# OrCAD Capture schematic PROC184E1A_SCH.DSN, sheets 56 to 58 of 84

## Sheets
56 60. RGMII1: size C; title: RGMII1; note: PROC184_SCH
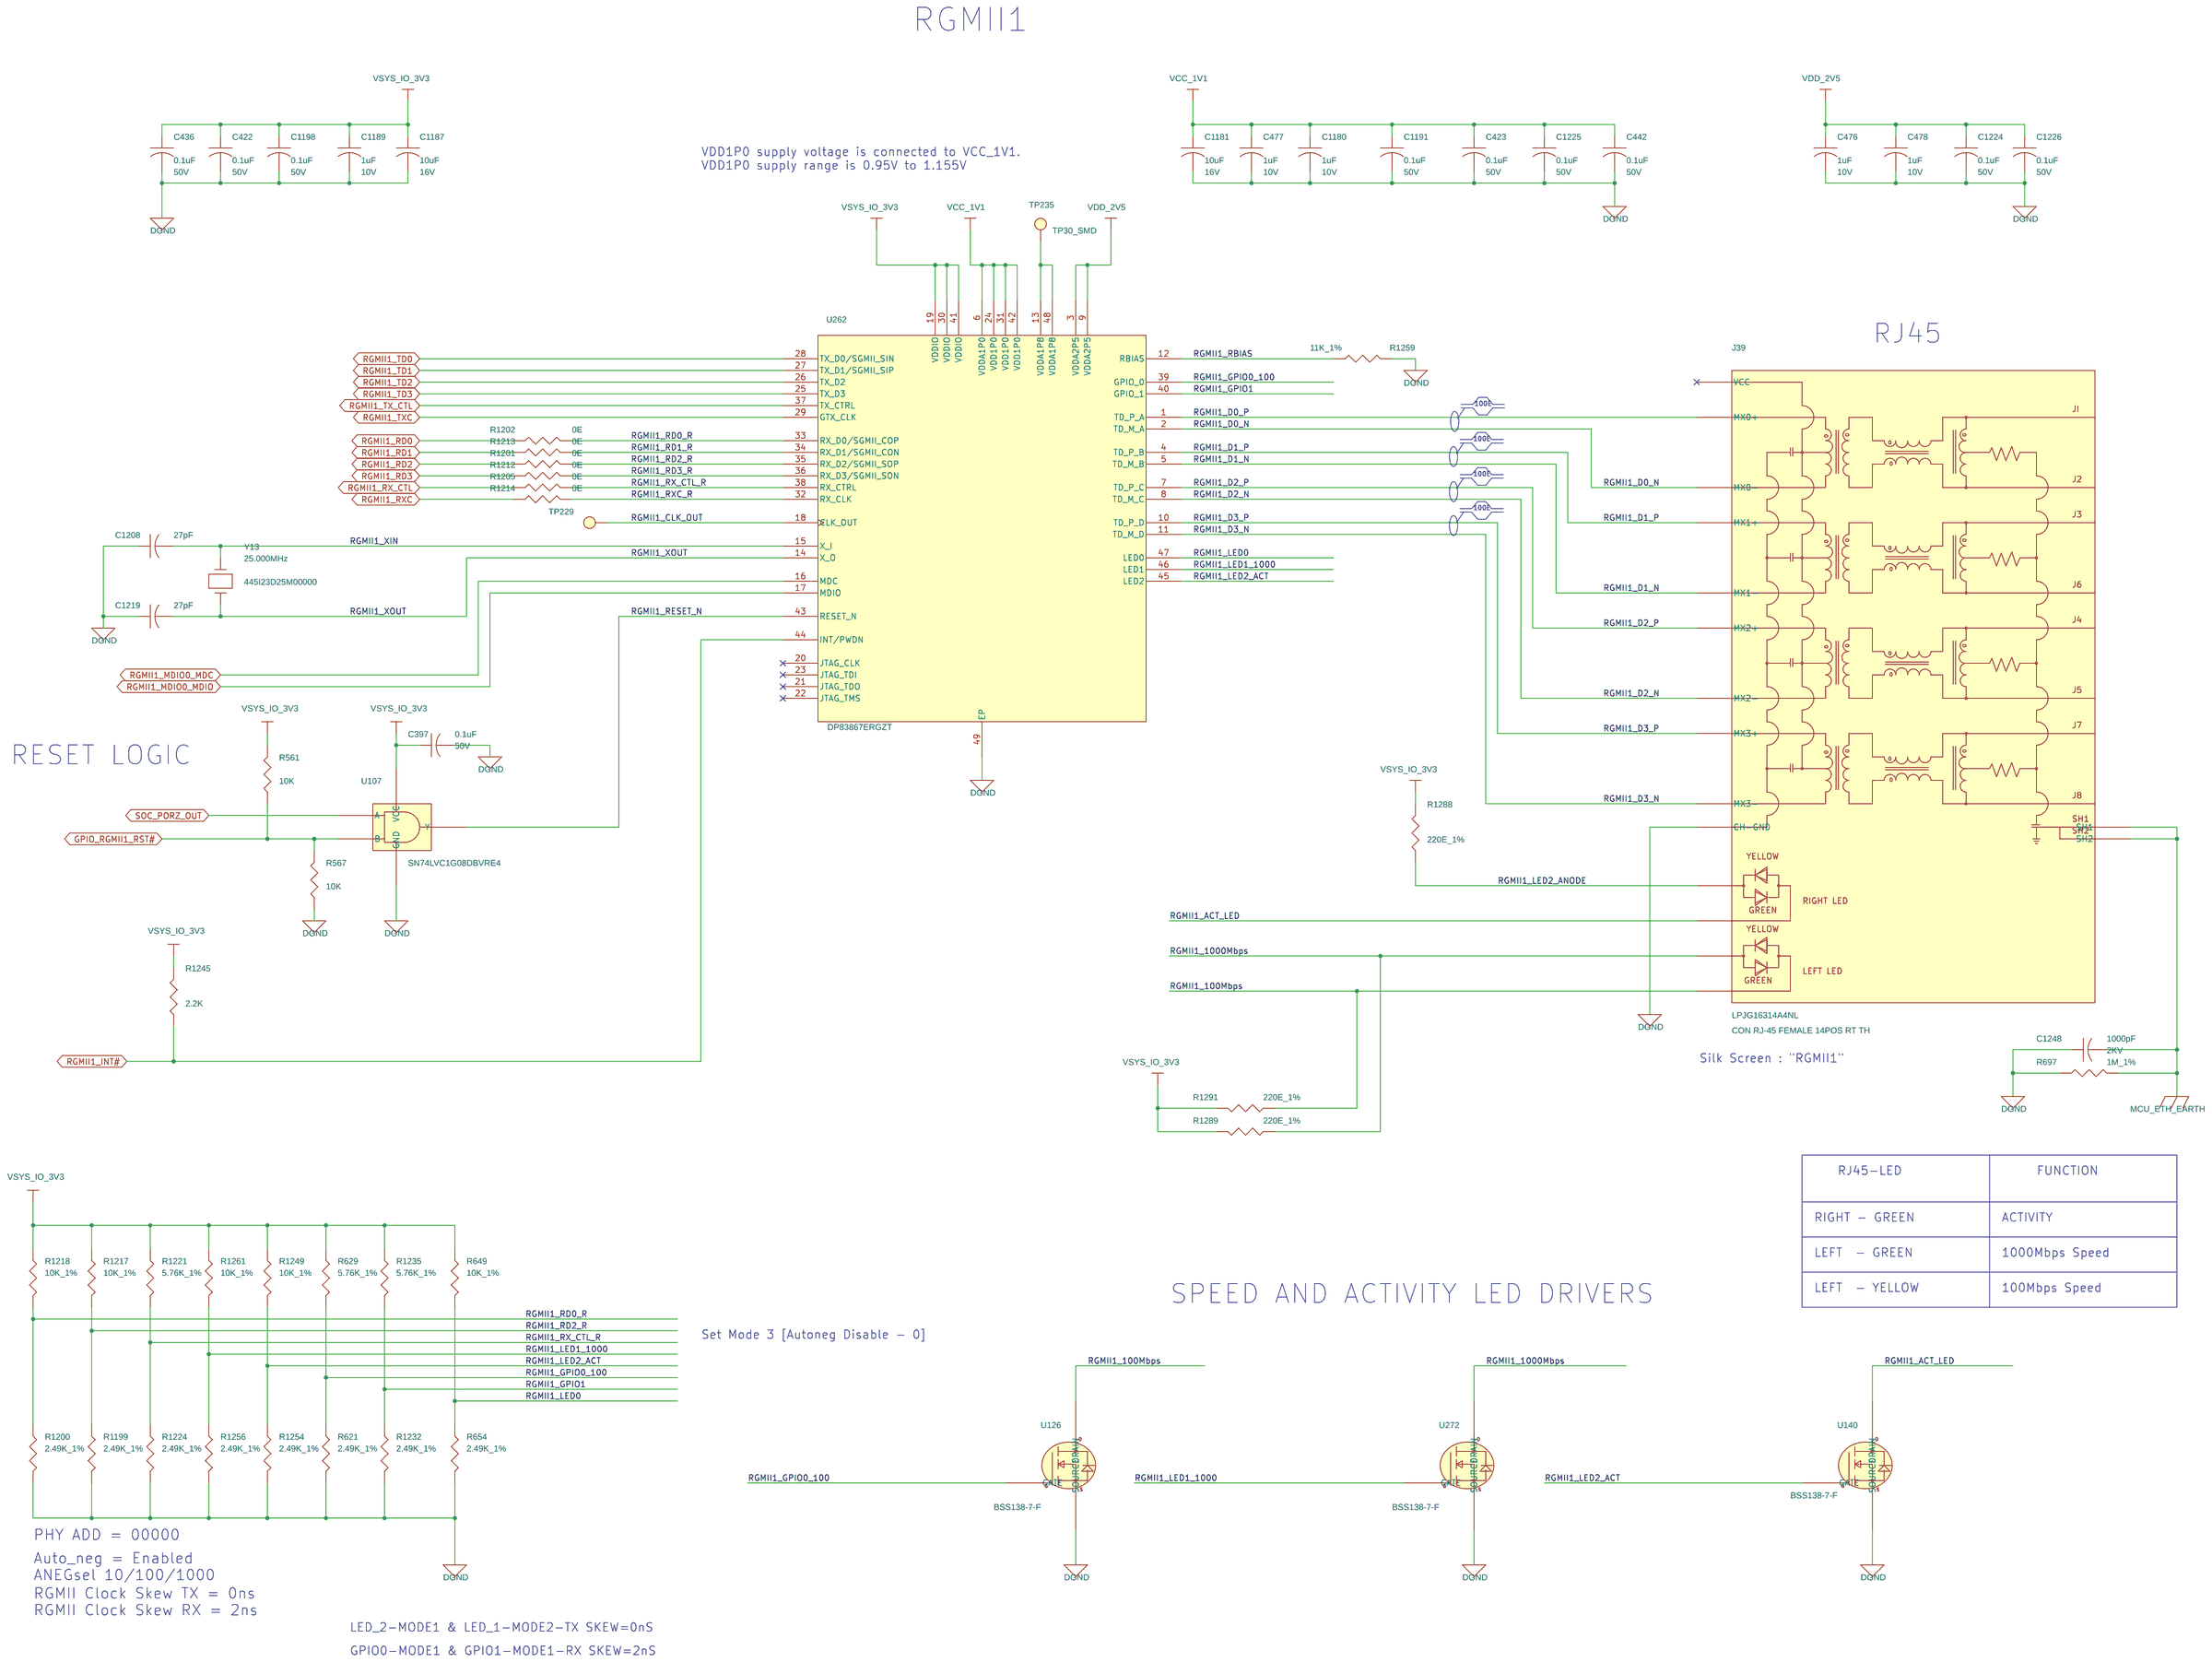
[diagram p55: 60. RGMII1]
57 65. DISPLAY PORT INTERFACE: size C; title: DISPLAY PORT INTERFACE; note: PROC184_SCH
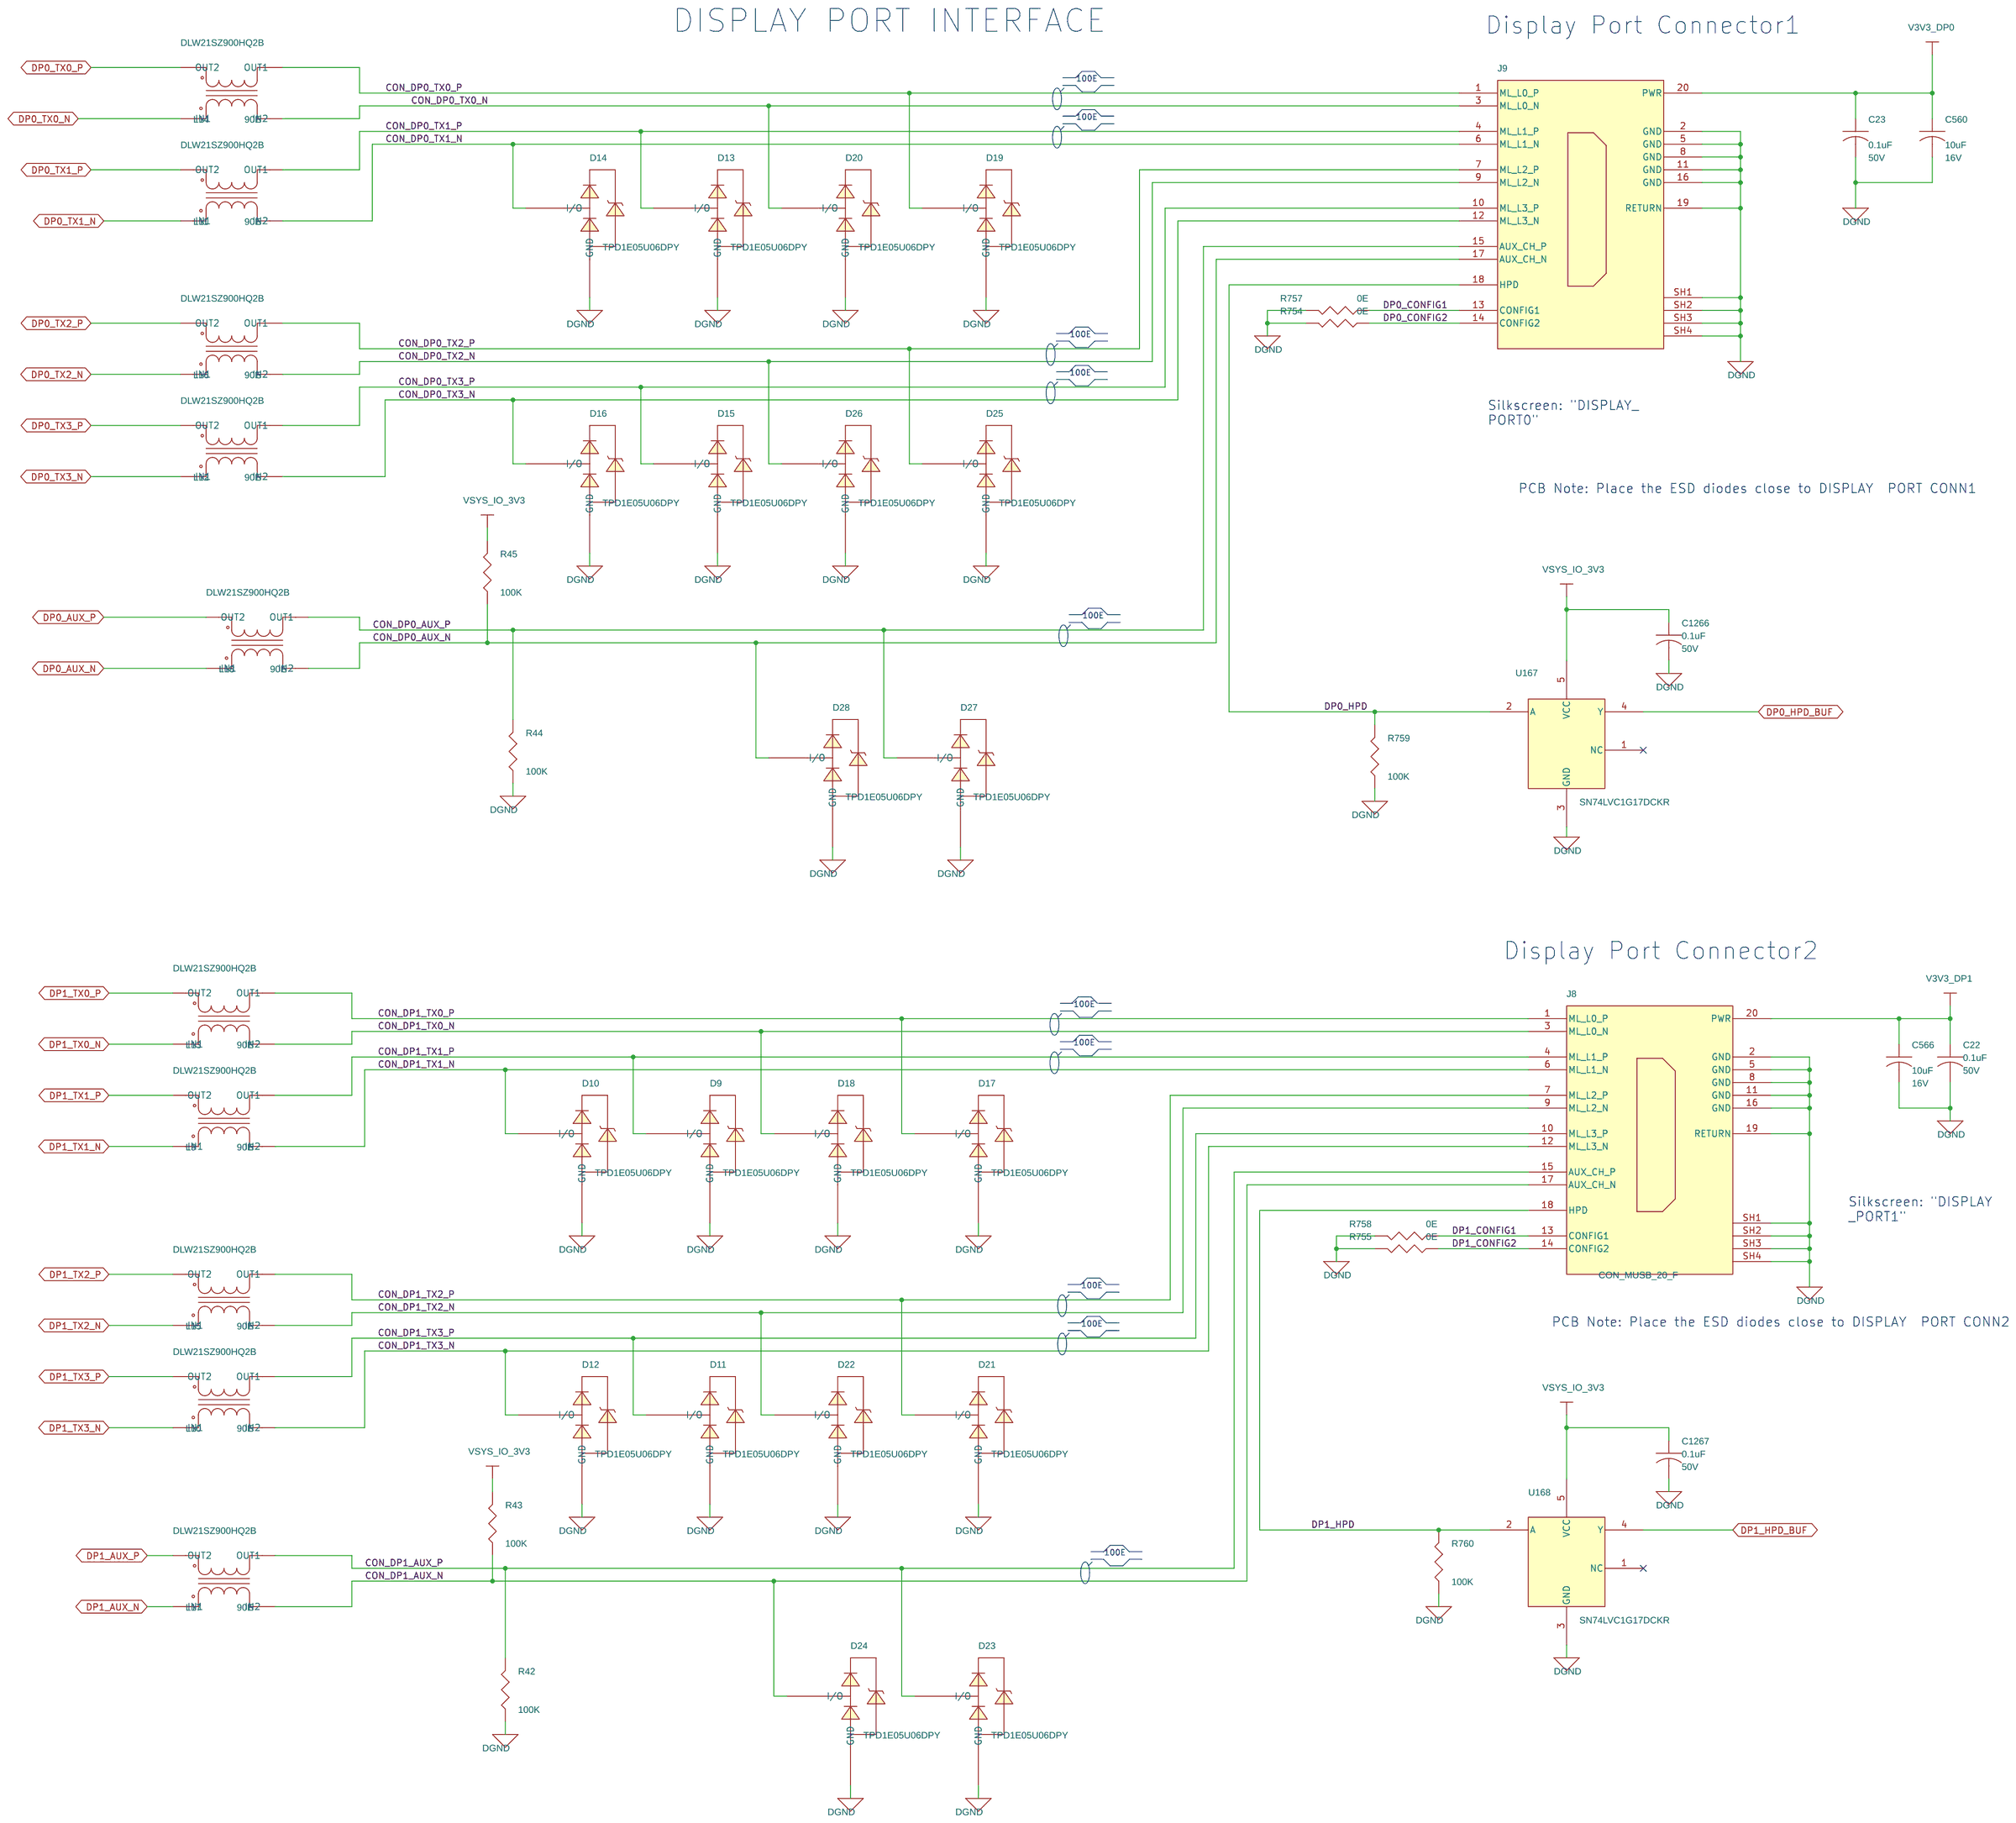
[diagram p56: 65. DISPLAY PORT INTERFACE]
58 66. ADC,RTC,I3C,APPLE AUTH: size C; title: ADC,RTC,I3C,APPLE AUTH_INTERFACE; note: PROC184_SCH
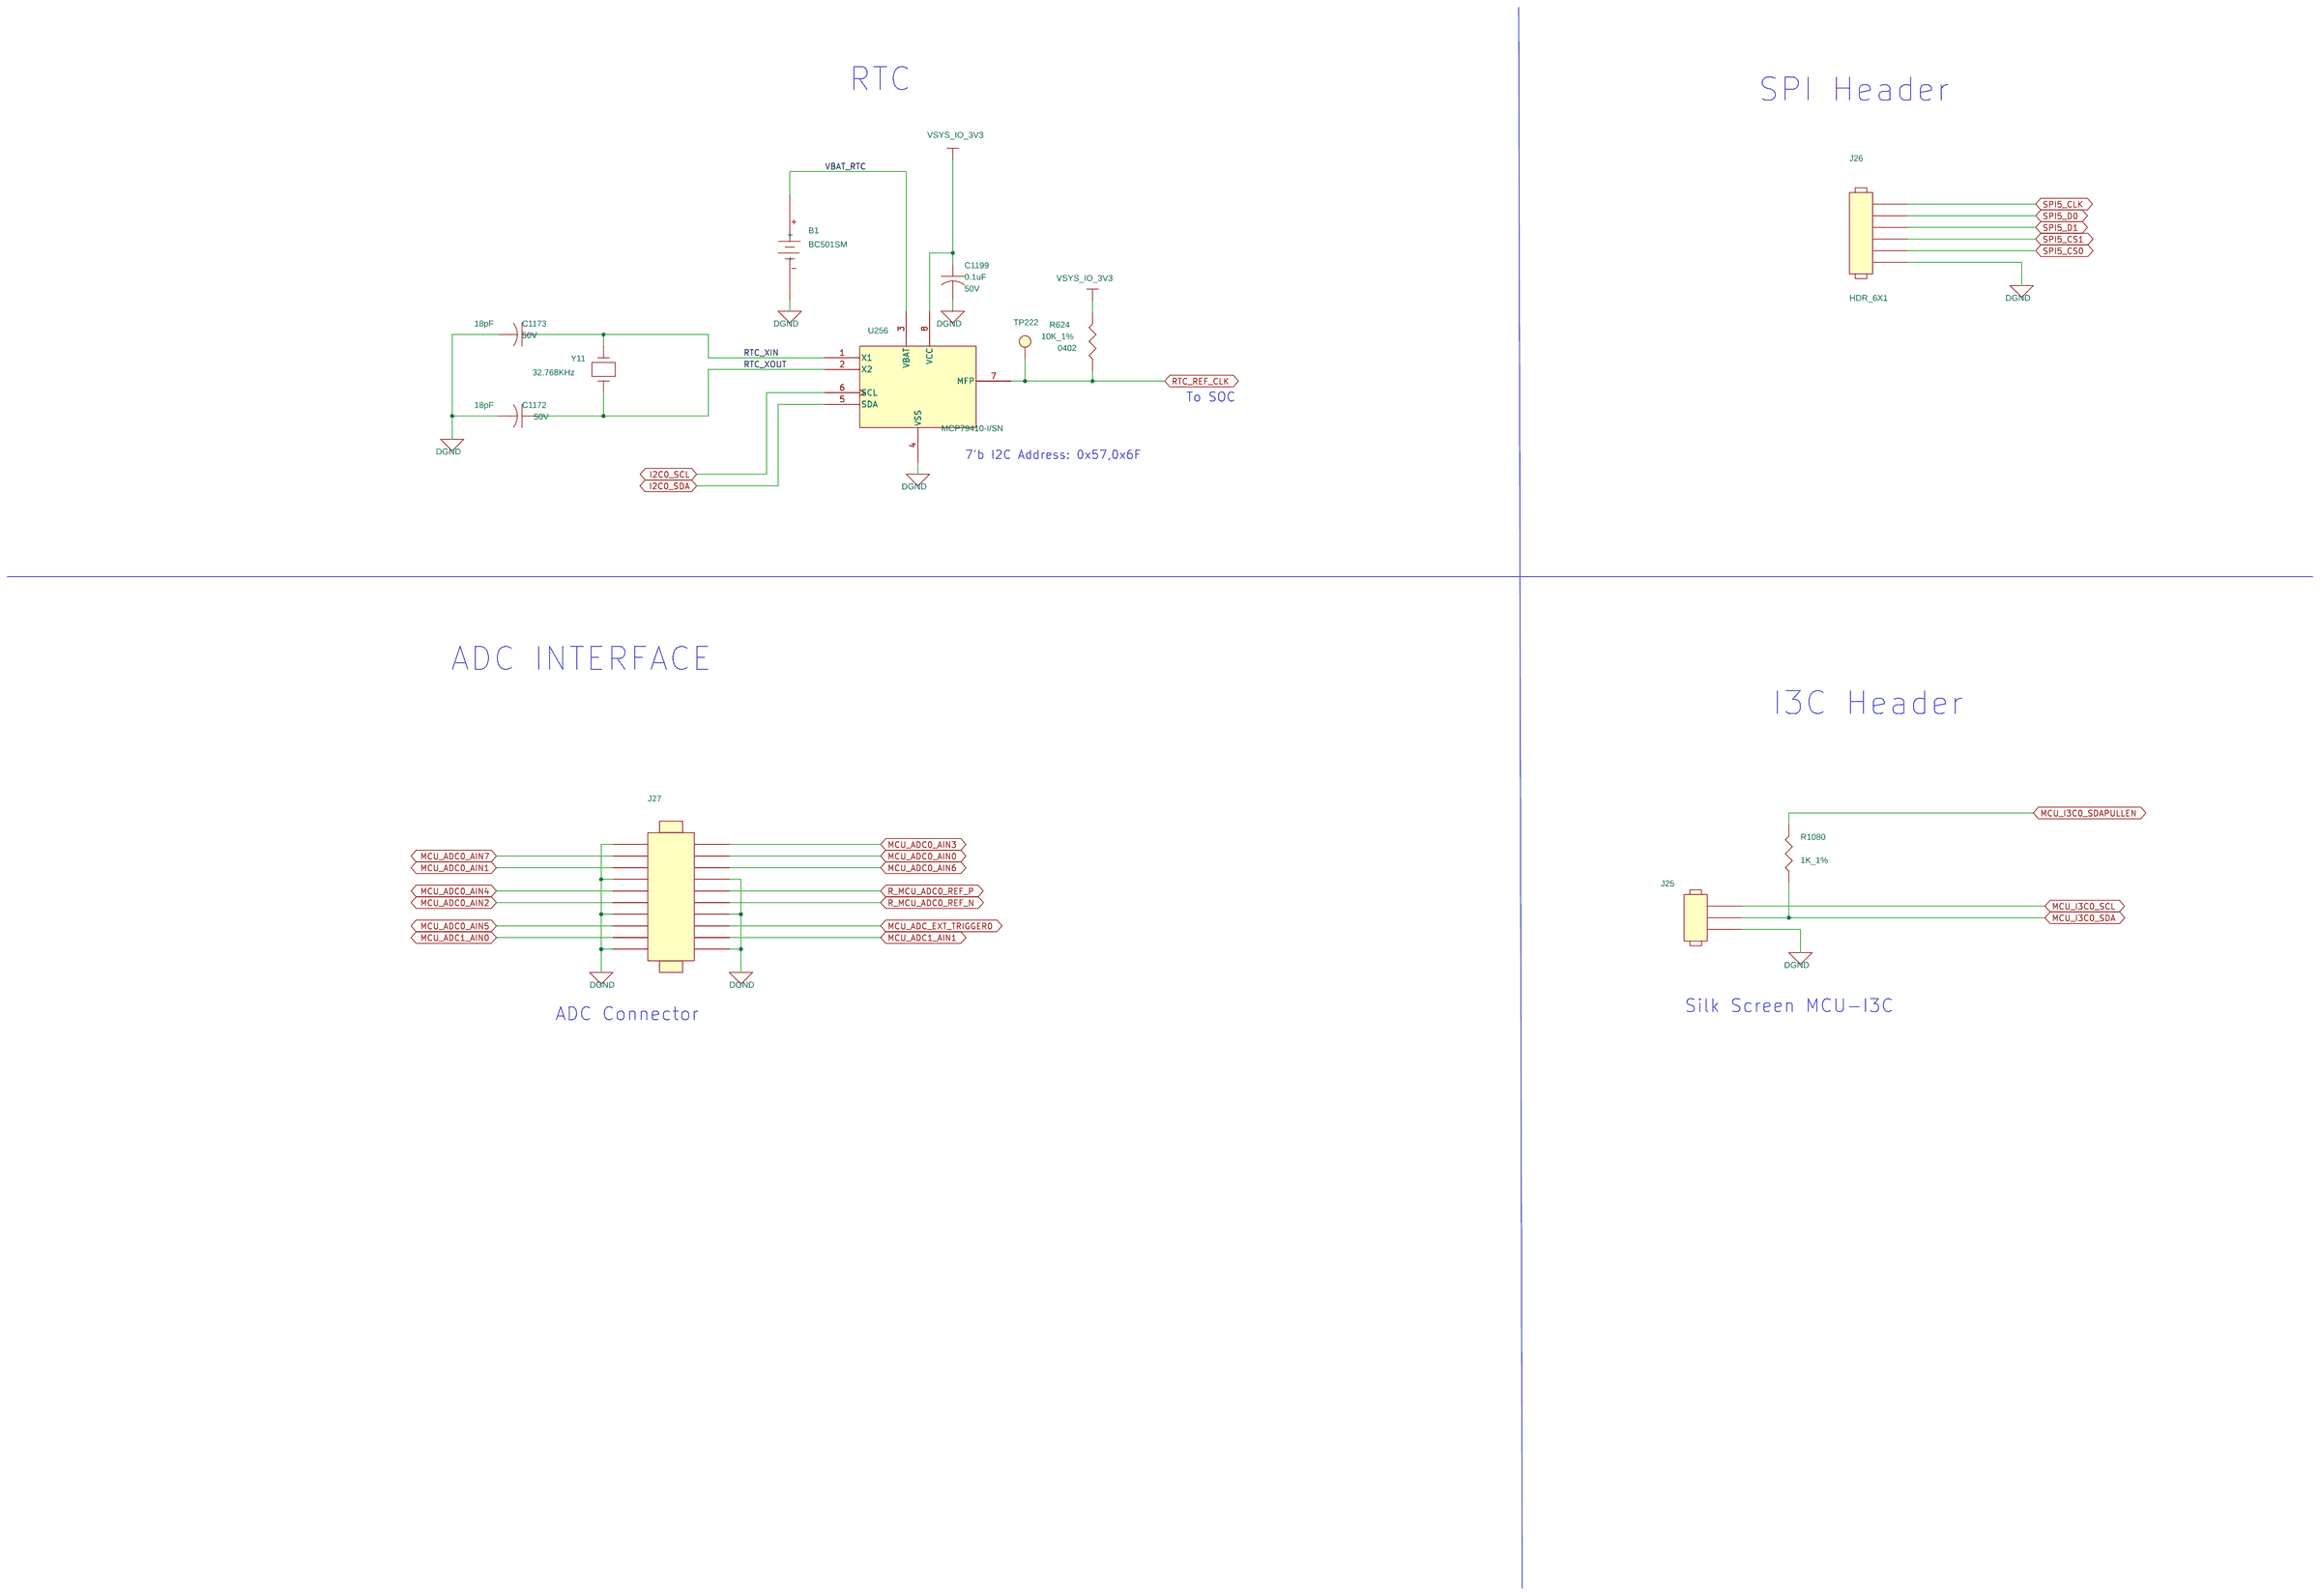
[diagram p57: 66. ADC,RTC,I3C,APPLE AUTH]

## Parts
sheet 60. RGMII1
C397  0.1uF  [CAP0402_0-75]
C422  0.1uF  [CAP0402_0-75]
C423  0.1uF  [CAP0402_0-75]
C436  0.1uF  [CAP0402_0-75]
C442  0.1uF  [CAP0402_0-75]
C476  1uF  [CAP0402_0-75]
C477  1uF  [CAP0402_0-75]
C478  1uF  [CAP0402_0-75]
C1180  1uF  [CAP0402_0-75]
C1181  10uF  [CAP0805_1-5]
C1187  10uF  [CAP0805_1-5]
C1189  1uF  [CAP0402_0-75]
C1191  0.1uF  [CAP0402_0-75]
C1198  0.1uF  [CAP0402_0-75]
C1208  27pF  [CAP0402_0-75]
C1219  27pF  [CAP0402_0-75]
C1224  0.1uF  [CAP0402_0-75]
C1225  0.1uF  [CAP0402_0-75]
C1226  0.1uF  [CAP0402_0-75]
C1248  1000pF  [CAP1206_1-75]
J39  CON_RJ45-14_LPJG16314A4NL  [CON_RJ45-14_LPJG16314A4NL_S_R_T_13-6]
R561  10K  [RES0402_0-5]
R567  10K  [RES0402_0-5]
R621  2.49K_1%  [RES0402_0-5]
R629  5.76K_1%  [RES0402_0-5]
R649  10K_1%  [RES0402_0-5]
R654  2.49K_1%  [RES0402_0-5]
R697  1M_1%  [RES0805_0-75]
R1199  2.49K_1%  [RES0402_0-5]
R1200  2.49K_1%  [RES0402_0-5]
R1201  0E  [RES0201_0-5]
R1202  0E  [RES0201_0-5]
R1205  0E  [RES0201_0-5]
R1212  0E  [RES0201_0-5]
R1213  0E  [RES0201_0-5]
R1214  0E  [RES0201_0-5]
R1217  10K_1%  [RES0402_0-5]
R1218  10K_1%  [RES0402_0-5]
R1221  5.76K_1%  [RES0402_0-5]
R1224  2.49K_1%  [RES0402_0-5]
R1232  2.49K_1%  [RES0402_0-5]
R1235  5.76K_1%  [RES0402_0-5]
R1245  2.2K  [RES0402_0-5]
R1249  10K_1%  [RES0402_0-5]
R1254  2.49K_1%  [RES0402_0-5]
R1256  2.49K_1%  [RES0402_0-5]
R1259  11K_1%  [RES0402_0-5]
R1261  10K_1%  [RES0402_0-5]
R1288  220E_1%  [RES0402_0-5]
R1289  220E_1%  [RES0402_0-5]
R1291  220E_1%  [RES0402_0-5]
TP229  TP30_SMD  [TP30_SMD]
TP235  TP30_SMD  [TP30_SMD]
U107  SN74LVC1G08DBVRE4  [SOT23-5]
U126  BSS138-7-F  [SOT23-123_1-1]
U140  BSS138-7-F  [SOT23-123_1-1]
U262  DP83867ERGZT  [VQFN48_19-68_285X285]
U272  BSS138-7-F  [SOT23-123_1-1]
Y13  25.000MHz  [XTAL_ABM3_205X130_SMD_1-4]
sheet 65. DISPLAY PORT INTERFACE
C22  0.1uF  [CAP0402_0-75]
C23  0.1uF  [CAP0402_0-75]
C560  10uF  [CAP0805_1-5]
C566  10uF  [CAP0805_1-5]
C1266  0.1uF  [CAP0402_0-75]
C1267  0.1uF  [CAP0402_0-75]
D9  TPD1E05U06DPY  [DIO_DFN0402_0-5]
D10  TPD1E05U06DPY  [DIO_DFN0402_0-5]
D11  TPD1E05U06DPY  [DIO_DFN0402_0-5]
D12  TPD1E05U06DPY  [DIO_DFN0402_0-5]
D13  TPD1E05U06DPY  [DIO_DFN0402_0-5]
D14  TPD1E05U06DPY  [DIO_DFN0402_0-5]
D15  TPD1E05U06DPY  [DIO_DFN0402_0-5]
D16  TPD1E05U06DPY  [DIO_DFN0402_0-5]
D17  TPD1E05U06DPY  [DIO_DFN0402_0-5]
D18  TPD1E05U06DPY  [DIO_DFN0402_0-5]
D19  TPD1E05U06DPY  [DIO_DFN0402_0-5]
D20  TPD1E05U06DPY  [DIO_DFN0402_0-5]
D21  TPD1E05U06DPY  [DIO_DFN0402_0-5]
D22  TPD1E05U06DPY  [DIO_DFN0402_0-5]
D23  TPD1E05U06DPY  [DIO_DFN0402_0-5]
D24  TPD1E05U06DPY  [DIO_DFN0402_0-5]
D25  TPD1E05U06DPY  [DIO_DFN0402_0-5]
D26  TPD1E05U06DPY  [DIO_DFN0402_0-5]
D27  TPD1E05U06DPY  [DIO_DFN0402_0-5]
D28  TPD1E05U06DPY  [DIO_DFN0402_0-5]
J8  CON_MUSB_20_F  [CON_USB20_472720001_S_R_T_7]
J9  CON_MUSB_20_F  [CON_USB20_472720001_S_R_T_7]
L9  90E  [IND4_DLW21H_90X60_SMD_1-4]
L10  90E  [IND4_DLW21H_90X60_SMD_1-4]
L11  90E  [IND4_DLW21H_90X60_SMD_1-4]
L12  90E  [IND4_DLW21H_90X60_SMD_1-4]
L13  90E  [IND4_DLW21H_90X60_SMD_1-4]
L14  90E  [IND4_DLW21H_90X60_SMD_1-4]
L15  90E  [IND4_DLW21H_90X60_SMD_1-4]
L16  90E  [IND4_DLW21H_90X60_SMD_1-4]
L17  90E  [IND4_DLW21H_90X60_SMD_1-4]
L18  90E  [IND4_DLW21H_90X60_SMD_1-4]
R42  100K  [RES0402_0-5]
R43  100K  [RES0402_0-5]
R44  100K  [RES0402_0-5]
R45  100K  [RES0402_0-5]
R754  0E  [RES0402_0-5]
R755  0E  [RES0402_0-5]
R757  0E  [RES0402_0-5]
R758  0E  [RES0402_0-5]
R759  100K  [RES0402_0-5]
R760  100K  [RES0402_0-5]
U167  SN74LVC1G17DCKR  [SC70-5]
U168  SN74LVC1G17DCKR  [SC70-5]
sheet 66. ADC,RTC,I3C,APPLE AUTH
B1  BC501SM  [BATTH_BC501SM_580X590_SMD_4-2]
C1172  18pF  [CAP0402_0-75]
C1173  18pF  [CAP0402_0-75]
C1199  0.1uF  [CAP0402_0-75]
J25  HDR_1X3  [HDR_3X1_100_S_T]
J26  HDR_6X1  [HDR_6X1_100_S_T]
J27  HDR_2X10  [HDR_2X10_TSW_100_S_T]
R624  10K_1%  [RES0402_0-5]
R1080  1K_1%  [RES0402_0-5]
TP222  TP40_SMD  [TP40_SMD]
U256  MCP79410-I/SN  [SOIC8_1-8]
Y11  32.768KHz  [XTAL_ABS07_130X60_SMD_0-9]

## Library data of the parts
C22 C23 C397 C422 C423 C436 C442 C1191 C1198 C1199 C1224-C1226 C1266 C1267 = CAP: CAP CERAMIC 0.1uF 50V 10% X7R 0402; Automotive Alternate_mfr_name: TDK; Automotive Alternate_mfr_part_number: CGA2B3X7R1H104K050BB; Chkd/date: MANIRAJA/261020; Crtd /date: ALVY/211020; Custom_Duty: 15%; Customs_HS_Code: 85322990; Direct Alternate_mfr_name: TDK; Direct Alternate_mfr_part_number: C1005X7R1H104K050BE; Distributor_name: DIGIKEY; Distributor_part_number: 490-10700-1-ND; Footprint Path: Y:\MIS_DATABASE\Library\ALTIUM_TOOL\PCB_FOOTPRINTS\Altium_Footprint_Lib.PcbLib; Height: 0.55MM; Library Path: Y:\MIS_DATABASE\Library\ALTIUM_TOOL\SCHEMATICS_PARTS\MS_DISCRETE_Library.schlib; Manufacturer: MURATA; Mfr_name: MURATA; Mfr_part_number: GRM155R71H104KE14D; Mistral Part No: 120011100014-R; Package: 0402; Part_type: CAPACITORS\CERAMIC; Project: J7_CP; RoHS: RoHS; Temperature: -55°C+125°C; Tolerance: 10%; Voltage: 50V; Wattage: NA; Weight: 3.1mg; Datasheet: Y:\MIS_DATABASE\DATASHEETS\CAPACITORS\GRM155R71H104KE14.PDF
C476-C478 C1180 C1189 = CAP: CAP CERAMIC 1uF 10V 10% X7S AUTO 0402; Automotive Alternate_mfr_name: TAIYO YUDEN; Automotive Alternate_mfr_part_number: EMK105BJ105KVHF; Chkd/date: MANIRAJA/100918; Crtd /date: ALVY/100918; Custom_Duty: 15%; Customs_HS_Code: 85322990; Direct Alternate_mfr_name: YAGEO AMERICA; Direct Alternate_mfr_part_number: CC0402KRX5R7BB105; Distributor_name: DIGIKEY; Distributor_part_number: 490-13409-1-ND; Footprint Path: Y:\MIS_DATABASE\Library\ALTIUM_TOOL\PCB_FOOTPRINTS\Altium_Footprint_Lib.PcbLib; Height: 0.70MM; Library Path: Y:\MIS_DATABASE\Library\ALTIUM_TOOL\SCHEMATICS_PARTS\MS_DISCRETE_Library.schlib; Manufacturer: TDK CORPORATION; Mfr_name: MURATA; Mfr_part_number: GCM155C71A105KE38D; Mistral Part No: 120018090021-R; Package: 0402; Part_type: CAPACITORS\CERAMIC; Project: SMART-M_SCRIPTALK_PB; RoHS: RoHS; Temperature: -55°C+125°C; Tolerance: 10%; Voltage: 10V; Wattage: NA; Weight: 6mg; Datasheet: Y:\MIS_DATABASE\DATASHEETS\CAPACITORS\MURATA-GCM-SER.PDF
C560 C566 C1181 C1187 = CAP: CAP CERAMIC 10uF 16V 10% X5R 0805; Automotive Alternate_mfr_name: TDK; Automotive Alternate_mfr_part_number: CGA4J1X7S1C106K125AC; Chkd/date: SHREESHAIL/220506; Crtd /date: MAZHAR/150506; Custom_Duty: 15%; Customs_HS_Code: 85322990; Direct Alternate_mfr_name: TDK; Direct Alternate_mfr_part_number: C2012X7S1C106K125AC; Distributor_name: DIGIKEY; Distributor_part_number: 490-3886-1-ND; Footprint Path: Y:\MIS_DATABASE\Library\ALTIUM_TOOL\PCB_FOOTPRINTS\Altium_Footprint_Lib.PcbLib; Height: 1.35MM; Library Path: Y:\MIS_DATABASE\Library\ALTIUM_TOOL\SCHEMATICS_PARTS\MS_DISCRETE_Library.schlib; Manufacturer: MURATA; Mfr_name: MURATA; Mfr_part_number: GRM21BR61C106KE15L; Mistral Part No: 120009030205-R; Package: 0805; Part_type: CAPACITORS\CERAMIC; Project: VOCERA; RoHS: RoHS; Temperature: -55°C+85°C; Tolerance: 10%; Voltage: 16V; Wattage: NA; Weight: 9.5mg; Datasheet: Y:\MIS_DATABASE\DATASHEETS\CAPACITORS\MURATA-GXX-SER_NOV17.PDF
C1208 C1219 = CAP: CAP CERAMIC 27pF 50V 5% C0G(NP0) 0402; Automotive Alternate_mfr_name: TDK; Automotive Alternate_mfr_part_number: CGA2B2C0G1H270J050BA; Chkd/date: MAZHAR/241208; Crtd /date: GEETHA/090606; Custom_Duty: 15%; Customs_HS_Code: 85322990; Direct Alternate_mfr_name: SAMSUNG; Direct Alternate_mfr_part_number: CL05C270JB5NNNC; Distributor_name: DIGIKEY; Distributor_part_number: 311-1019-1-ND; Footprint Path: Y:\MIS_DATABASE\Library\ALTIUM_TOOL\PCB_FOOTPRINTS\Altium_Footprint_Lib.PcbLib; Height: 0.55MM; Library Path: Y:\MIS_DATABASE\Library\ALTIUM_TOOL\SCHEMATICS_PARTS\MS_DISCRETE_Library.schlib; Manufacturer: YAGEO AMERICA; Mfr_name: YAGEO AMERICA; Mfr_part_number: CC0402JRNPO9BN270; Mistral Part No: 120014100024-R; Package: 0402; Part_type: CAPACITORS\CERAMIC; Project: PNAV; RoHS: RoHS; Temperature: -55°C+125°C; Tolerance: 5%; Voltage: 50V; Wattage: NA; Weight: 0.65mg; Datasheet: Y:\MIS_DATABASE\DATASHEETS\CAPACITORS\YACC-NPO.PDF
C1248 = CAP: CAP CERAMIC 1000pF 2KV 10% X7R 1206; Automotive Alternate_mfr_name: KEMET; Automotive Alternate_mfr_part_number: C1206X102KGRACAUTO; Chkd/date: SHREESHAIL/291106; Crtd /date: MAZHAR/281106; Custom_Duty: 15%; Customs_HS_Code: 85322990; Direct Alternate_mfr_name: KEMET; Direct Alternate_mfr_part_number: C1206C102KGRACTU; Distributor_name: DIGIKEY; Distributor_part_number: 478-2956-1-ND; Footprint Path: Y:\MIS_DATABASE\Library\ALTIUM_TOOL\PCB_FOOTPRINTS\Altium_Footprint_Lib.PcbLib; Height: 1.52MM; Library Path: Y:\MIS_DATABASE\Library\ALTIUM_TOOL\SCHEMATICS_PARTS\MS_DISCRETE_Library.schlib; Manufacturer: AVX CORPORATION; Mfr_name: AVX CORPORATION; Mfr_part_number: 1206GC102KAT1A; Mistral Part No: 120015080006-R; Package: 1206; Part_type: CAPACITORS\CERAMIC; Project: ADR1B; RoHS: RoHS; Temperature: -55°C+125°C; Tolerance: 10%; Voltage: 2KV; Wattage: NA; Weight: 16.2mg; Datasheet: Y:\MIS_DATABASE\DATASHEETS\CAPACITORS\AVX_HV-MLC.PDF
J39 = CON_RJ45-14_LPJG16314A4NL: CON RJ-45 FEMALE 14POS RT TH; Chkd/date: VASANTHA/150714; Crtd /date: BALACHANDAR/120614; Custom_Duty: 24%; Customs_HS_Code: 85369090; Distributor_name: NA; Distributor_part_number: NA; Footprint Path: Y:\MIS_DATABASE\Library\ALTIUM_TOOL\PCB_FOOTPRINTS\Altium_Footprint_Lib.PcbLib; Height: 13.60MM; Library Path: Y:\MIS_DATABASE\Library\ALTIUM_TOOL\SCHEMATICS_PARTS\MS_CONNECTOR_Library.schlib; Manufacturer: LINK-PP; Mfr_name: LINK-PP; Mfr_part_number: LPJG16314A4NL; Mistral Part No: 150014060029-R; Package: THRU-HOLE; Part_type: CONNECTOR\JACK; Project: AEGIS; RoHS: RoHS; Temperature: -0°C+70°C; Tolerance: NA; Voltage: NA; Wattage: NA; Weight: NA; Datasheet: Y:\MIS_DATABASE\DATASHEETS\CONNECTORS\LPJG16314A4NL.PDF
R561 = RESISTOR: RES 10K 1/16W 5% 0402; Chkd/date: VASANTHA/061216; Crtd /date: MAZHAR/230805; Custom_Duty: 15%; Customs_HS_Code: 85332119; Distributor_name: DIGIKEY; Distributor_part_number: 311-10KJRCT-ND; Footprint Path: Y:\MIS_DATABASE\Library\ALTIUM_TOOL\PCB_FOOTPRINTS\Altium_Footprint_Lib.PcbLib; Height: 0.40MM; Library Path: Y:\MIS_DATABASE\Library\ALTIUM_TOOL\SCHEMATICS_PARTS\MS_DISCRETE_Library.schlib; Manufacturer: YAGEO AMERICA; Mfr_name: YAGEO AMERICA; Mfr_part_number: RC0402JR-0710KL; Mistral Part No: 110011060021-R; Package: 0402; Part_type: RESISTORS\FIXED; Project: HSE; RoHS: RoHS; Temperature: -55°C+155°C; Tolerance: 5%; Voltage: NA; Wattage: 1/16W; Weight: 0.65mg; Datasheet: Y:\MIS_DATABASE\DATASHEETS\RESISTORS\RCXXXXL-SER_MAR18.PDF
R567 = RESISTOR: RES 10K 1/16W 5% 0402; Assembly_Instruction: DNI; Chkd/date: VASANTHA/061216; Crtd /date: MAZHAR/230805; Custom_Duty: 15%; Customs_HS_Code: 85332119; Distributor_name: DIGIKEY; Distributor_part_number: 311-10KJRCT-ND; Footprint Path: Y:\MIS_DATABASE\Library\ALTIUM_TOOL\PCB_FOOTPRINTS\Altium_Footprint_Lib.PcbLib; Height: 0.40MM; Library Path: Y:\MIS_DATABASE\Library\ALTIUM_TOOL\SCHEMATICS_PARTS\MS_DISCRETE_Library.schlib; Manufacturer: YAGEO AMERICA; Mfr_name: YAGEO AMERICA; Mfr_part_number: RC0402JR-0710KL; Mistral Part No: 110011060021-R; Package: 0402; Part_type: RESISTORS\FIXED; Project: HSE; RoHS: RoHS; Temperature: -55°C+155°C; Tolerance: 5%; Voltage: NA; Wattage: 1/16W; Weight: 0.65mg; Datasheet: Y:\MIS_DATABASE\DATASHEETS\RESISTORS\RCXXXXL-SER_MAR18.PDF
R621 R654 R1199 R1200 R1232 R1254 = RESISTOR: RES 2.49K 1/16W 1% 0402; Assembly_Instruction: DNI; Chkd/date: VASANTHA/270516; Crtd /date: VASANTHA/270516; Custom_Duty: 15%; Customs_HS_Code: 85332119; Distributor_name: DIGIKEY; Distributor_part_number: 311-2.49KLRCT-ND; Footprint Path: Y:\MIS_DATABASE\Library\ALTIUM_TOOL\PCB_FOOTPRINTS\Altium_Footprint_Lib.PcbLib; Height: 0.40MM; Library Path: Y:\MIS_DATABASE\Library\ALTIUM_TOOL\SCHEMATICS_PARTS\MS_DISCRETE_Library.schlib; Manufacturer: YAGEO AMERICA; Mfr_name: YAGEO AMERICA; Mfr_part_number: RC0402FR-072K49L; Mistral Part No: 110016050020-R; Package: 0402; Part_type: RESISTORS\FIXED; Project: TMDXCSKCC; RoHS: RoHS; Temperature: -55°C+155°C; Tolerance: 1%; Voltage: NA; Wattage: 1/16W; Weight: 0.65mg; Datasheet: Y:\MIS_DATABASE\DATASHEETS\RESISTORS\RCXXXXL-SER_MAR18.PDF
R629 R1235 = RESISTOR: RES 5.76K 1/10W 1% 0402; Assembly_Instruction: DNI; Chkd/date: MAZHAR/150709; Crtd /date: USMAN/220808; Custom_Duty: 15%; Customs_HS_Code: 85332119; Distributor_name: DIGIKEY; Distributor_part_number: P5.76KLCT-ND; Footprint Path: Y:\MIS_DATABASE\Library\ALTIUM_TOOL\PCB_FOOTPRINTS\Altium_Footprint_Lib.PcbLib; Height: 0.40MM; Library Path: Y:\MIS_DATABASE\Library\ALTIUM_TOOL\SCHEMATICS_PARTS\MS_DISCRETE_Library.schlib; Manufacturer: PANASONIC-ECG; Mfr_name: PANASONIC-ECG; Mfr_part_number: ERJ-2RKF5761X; Mistral Part No: 110009030945-R; Package: 0402; Part_type: RESISTORS\FIXED; Project: CPB; RoHS: RoHS; Temperature: -55°C+155°C; Tolerance: 1%; Voltage: NA; Wattage: 1/10W; Weight: 0.8mg; Datasheet: Y:\MIS_DATABASE\DATASHEETS\RESISTORS\PAN-ERJSER_NOV17.PDF
R649 R1217 R1218 R1249 = RESISTOR: RES 10K 1/16W 1% 0402; Assembly_Instruction: DNI; Chkd/date: VASANTHA/201216; Crtd /date: GEETHA/290506; Custom_Duty: 15%; Customs_HS_Code: 85332119; Distributor_name: DIGIKEY; Distributor_part_number: 311-10.0KLRTR-ND; Footprint Path: Y:\MIS_DATABASE\Library\ALTIUM_TOOL\PCB_FOOTPRINTS\Altium_Footprint_Lib.PcbLib; Height: 0.40MM; Library Path: Y:\MIS_DATABASE\Library\ALTIUM_TOOL\SCHEMATICS_PARTS\MS_DISCRETE_Library.schlib; Manufacturer: YAGEO AMERICA; Mfr_name: YAGEO AMERICA; Mfr_part_number: RC0402FR-0710KL; Mistral Part No: 110015090015-R; Package: 0402; Part_type: RESISTORS\FIXED; Project: VOCERA; RoHS: RoHS; Temperature: -55°C+155°C; Tolerance: 1%; Voltage: NA; Wattage: 1/16W; Weight: 0.65mg; Datasheet: Y:\MIS_DATABASE\DATASHEETS\RESISTORS\RCXXXXL-SER_MAR18.PDF
R697 = RESISTOR: RES 1M 1/8W 1% 0805; Chkd/date: VASANTHA/150514; Crtd /date: BALACHANDAR/150514; Custom_Duty: 15%; Customs_HS_Code: 85332119; Distributor_name: DIGIKEY; Distributor_part_number: P1.00MCCT-ND; Footprint Path: Y:\MIS_DATABASE\Library\ALTIUM_TOOL\PCB_FOOTPRINTS\Altium_Footprint_Lib.PcbLib; Height: 0.70MM; Library Path: Y:\MIS_DATABASE\Library\ALTIUM_TOOL\SCHEMATICS_PARTS\MS_DISCRETE_Library.schlib; Manufacturer: PANASONIC-ECG; Mfr_name: PANASONIC-ECG; Mfr_part_number: ERJ-6ENF1004V; Mistral Part No: 110014100002-R; Package: 0805; Part_type: RESISTORS\FIXED; Project: HUMANWARE_PHOENIX; RoHS: RoHS; Temperature: -55°C+155°C; Tolerance: 1%; Voltage: NA; Wattage: 1/8W; Weight: 4mg; Datasheet: Y:\MIS_DATABASE\DATASHEETS\RESISTORS\PAN-ERJSER_NOV17.PDF
R1201 R1202 R1205 R1212-R1214 = RESISTOR: RES 0E 1/20W 5% 0201; Chkd/date: NAVEED/301214; Crtd /date: MUDDU/120710; Custom_Duty: 15%; Customs_HS_Code: 85332119; Distributor_name: DIGIKEY; Distributor_part_number: 311-0.0NCT-ND; Footprint Path: Y:\MIS_DATABASE\Library\ALTIUM_TOOL\PCB_FOOTPRINTS\Altium_Footprint_Lib.PcbLib; Height: 0.26MM; Library Path: Y:\MIS_DATABASE\Library\ALTIUM_TOOL\SCHEMATICS_PARTS\MS_DISCRETE_Library.schlib; Manufacturer: YAGEO AMERICA; Mfr_name: YAGEO AMERICA; Mfr_part_number: RC0201JR-070RL; Mistral Part No: 110010070067-R; Package: 0201; Part_type: RESISTORS\FIXED; Project: PB_BUGBASE; RoHS: RoHS; Temperature: -55°C+125°C; Tolerance: 5%; Voltage: NA; Wattage: 1/20W; Weight: 0.17mg; Datasheet: Y:\MIS_DATABASE\DATASHEETS\RESISTORS\RCXXXXL-SER_MAR18.PDF
R1221 = RESISTOR: RES 5.76K 1/10W 1% 0402; Chkd/date: MAZHAR/150709; Crtd /date: USMAN/220808; Custom_Duty: 15%; Customs_HS_Code: 85332119; Distributor_name: DIGIKEY; Distributor_part_number: P5.76KLCT-ND; Footprint Path: Y:\MIS_DATABASE\Library\ALTIUM_TOOL\PCB_FOOTPRINTS\Altium_Footprint_Lib.PcbLib; Height: 0.40MM; Library Path: Y:\MIS_DATABASE\Library\ALTIUM_TOOL\SCHEMATICS_PARTS\MS_DISCRETE_Library.schlib; Manufacturer: PANASONIC-ECG; Mfr_name: PANASONIC-ECG; Mfr_part_number: ERJ-2RKF5761X; Mistral Part No: 110009030945-R; Package: 0402; Part_type: RESISTORS\FIXED; Project: CPB; RoHS: RoHS; Temperature: -55°C+155°C; Tolerance: 1%; Voltage: NA; Wattage: 1/10W; Weight: 0.8mg; Datasheet: Y:\MIS_DATABASE\DATASHEETS\RESISTORS\PAN-ERJSER_NOV17.PDF
R1224 R1256 = RESISTOR: RES 2.49K 1/16W 1% 0402; Chkd/date: VASANTHA/270516; Crtd /date: VASANTHA/270516; Custom_Duty: 15%; Customs_HS_Code: 85332119; Distributor_name: DIGIKEY; Distributor_part_number: 311-2.49KLRCT-ND; Footprint Path: Y:\MIS_DATABASE\Library\ALTIUM_TOOL\PCB_FOOTPRINTS\Altium_Footprint_Lib.PcbLib; Height: 0.40MM; Library Path: Y:\MIS_DATABASE\Library\ALTIUM_TOOL\SCHEMATICS_PARTS\MS_DISCRETE_Library.schlib; Manufacturer: YAGEO AMERICA; Mfr_name: YAGEO AMERICA; Mfr_part_number: RC0402FR-072K49L; Mistral Part No: 110016050020-R; Package: 0402; Part_type: RESISTORS\FIXED; Project: TMDXCSKCC; RoHS: RoHS; Temperature: -55°C+155°C; Tolerance: 1%; Voltage: NA; Wattage: 1/16W; Weight: 0.65mg; Datasheet: Y:\MIS_DATABASE\DATASHEETS\RESISTORS\RCXXXXL-SER_MAR18.PDF
R1245 = RESISTOR: RES 2.2K 1/16W 5% 0402; Chkd/date: VASANTHA/061216; Crtd /date: BAVISH/021210; Custom_Duty: 15%; Customs_HS_Code: 85332119; Distributor_name: DIGIKEY; Distributor_part_number: 311-2.2KJRCT-ND; Footprint Path: Y:\MIS_DATABASE\Library\ALTIUM_TOOL\PCB_FOOTPRINTS\Altium_Footprint_Lib.PcbLib; Height: 0.40MM; Library Path: Y:\MIS_DATABASE\Library\ALTIUM_TOOL\SCHEMATICS_PARTS\MS_DISCRETE_Library.schlib; Manufacturer: YAGEO AMERICA; Mfr_name: YAGEO AMERICA; Mfr_part_number: RC0402JR-072K2L; Mistral Part No: 110010120018-R; Package: 0402; Part_type: RESISTORS\FIXED; Project: TE4; RoHS: RoHS; Temperature: -55°C+155°C; Tolerance: 5%; Voltage: NA; Wattage: 1/16W; Weight: 0.65mg; Datasheet: Y:\MIS_DATABASE\DATASHEETS\RESISTORS\RCXXXXL-SER_MAR18.PDF
R1259 = RESISTOR: RES 11K 1/16W 1% 0402; Chkd/date: VASANTHA/251115; Crtd /date: VASANTHA/251115; Custom_Duty: 15%; Customs_HS_Code: 85332119; Distributor_name: DIGIKEY; Distributor_part_number: 311-11.0KLRCT-ND; Footprint Path: Y:\MIS_DATABASE\Library\ALTIUM_TOOL\PCB_FOOTPRINTS\Altium_Footprint_Lib.PcbLib; Height: 0.40MM; Library Path: Y:\MIS_DATABASE\Library\ALTIUM_TOOL\SCHEMATICS_PARTS\MS_DISCRETE_Library.schlib; Manufacturer: YAGEO AMERICA; Mfr_name: YAGEO AMERICA; Mfr_part_number: RC0402FR-0711KL; Mistral Part No: 110015110012-R; Package: 0402; Part_type: RESISTORS\FIXED; Project: TI_VLAN_SWITCH; RoHS: RoHS; Temperature: -55°C+155°C; Tolerance: 1%; Voltage: NA; Wattage: 1/16W; Weight: 0.65mg; Datasheet: Y:\MIS_DATABASE\DATASHEETS\RESISTORS\RCXXXXL-SER_MAR18.PDF
R624 R1261 = RESISTOR: RES 10K 1/16W 1% 0402; Chkd/date: VASANTHA/201216; Crtd /date: GEETHA/290506; Custom_Duty: 15%; Customs_HS_Code: 85332119; Distributor_name: DIGIKEY; Distributor_part_number: 311-10.0KLRTR-ND; Footprint Path: Y:\MIS_DATABASE\Library\ALTIUM_TOOL\PCB_FOOTPRINTS\Altium_Footprint_Lib.PcbLib; Height: 0.40MM; Library Path: Y:\MIS_DATABASE\Library\ALTIUM_TOOL\SCHEMATICS_PARTS\MS_DISCRETE_Library.schlib; Manufacturer: YAGEO AMERICA; Mfr_name: YAGEO AMERICA; Mfr_part_number: RC0402FR-0710KL; Mistral Part No: 110015090015-R; Package: 0402; Part_type: RESISTORS\FIXED; Project: VOCERA; RoHS: RoHS; Temperature: -55°C+155°C; Tolerance: 1%; Voltage: NA; Wattage: 1/16W; Weight: 0.65mg; Datasheet: Y:\MIS_DATABASE\DATASHEETS\RESISTORS\RCXXXXL-SER_MAR18.PDF
R1288 R1289 R1291 = RESISTOR: RES 220E 1/16W 1% 0402; Chkd/date: MANIRAJA/130917; Crtd /date: MANIRAJA/130917; Custom_Duty: 15%; Customs_HS_Code: 85332119; Distributor_name: DIGIKEY; Distributor_part_number: 311-220LRCT-ND; Footprint Path: Y:\MIS_DATABASE\Library\ALTIUM_TOOL\PCB_FOOTPRINTS\Altium_Footprint_Lib.PcbLib; Height: 0.40MM; Library Path: Y:\MIS_DATABASE\Library\ALTIUM_TOOL\SCHEMATICS_PARTS\MS_DISCRETE_Library.schlib; Manufacturer: YAGEO AMERICA; Mfr_name: YAGEO AMERICA; Mfr_part_number: RC0402FR-07220RL; Mistral Part No: 110019040169-R; Package: 0402; Part_type: RESISTORS\FIXED; Project: TI_SVB_MAXWELL_DUT; RoHS: RoHS; Temperature: -55°C+155°C; Tolerance: 1%; Voltage: NA; Wattage: 1/16W; Weight: 0.65mg; Datasheet: Y:\MIS_DATABASE\DATASHEETS\RESISTORS\RCXXXXL-SER_MAR18.PDF
TP229 TP235 = TESTPOINT: TESTPOINT CIR 30 SMD; Chkd/date: SHREESHAIL/171006; Crtd /date: MAZHAR/171006; Custom_Duty: NA; Customs_HS_Code: NA; Distributor_name: NA; Distributor_part_number: NA; Footprint Path: Y:\MIS_DATABASE\Library\ALTIUM_TOOL\PCB_FOOTPRINTS\Altium_Footprint_Lib.PcbLib; Height: NA; Library Path: Y:\MIS_DATABASE\Library\ALTIUM_TOOL\SCHEMATICS_PARTS\MS_DISCRETE_Library.schlib; MECHANICAL 3D STEP FILE: NA; Manufacturer: LOCAL; Mfr_name: LOCAL; Mistral Part No: 130009030930; Package: SMD; Project: BT MODULE_CSRBC04; RoHS: NA; Temperature: NA; Tolerance: NA; Voltage: NA; Wattage: NA; Weight: NA; Datasheet: NA
U107 = SN74LVC1G08DBVRE4_SOT23-5: IC SINGLE 2-INPUT POSITIVE AND GATE SOT23-5; Automotive Alternate_mfr_name: TEXAS INSTRUMENTS; Automotive Alternate_mfr_part_number: SN74LVC1G08QDBVRQ1; Chkd/date: SUHAS/221010; Crtd /date: USMAN/151008; Custom_Duty: 15%; Customs_HS_Code: 85423100; Distributor_name: DIGIKEY; Distributor_part_number: SN74LVC1G08DBVRE4-ND; Height: 1.45MM; Manufacturer: TEXAS INSTRUMENTS; Mfr_name: TEXAS INSTRUMENTS; Mistral Part No: 141009060026-R; Part_type: ICS\DIGITAL\GATES; Project: KHAN_MAIN; RoHS: Sb/ Br FREE; Temperature: -40°C+85°C; Datasheet: Y:\MIS_DATABASE\DATASHEETS\ICS\DIGITAL\GATES\SN74LVC1G08.PDF
U126 U140 U272 = MOSFET_2N7002_SOT23: IC MOSFET N-CHANNEL 50V 200mA SOT23-123; Chkd/date: MANIRAJA/190618; Crtd /date: USMAN/240709; Custom_Duty: 15%; Customs_HS_Code: 85423100; Distributor_name: DIGIKEY; Distributor_part_number: BSS138-FDICT-ND; Footprint Path: Y:\MIS_DATABASE\Library\ALTIUM_TOOL\PCB_FOOTPRINTS\Altium_Footprint_Lib.PcbLib; Height: 1.10MM; Library Path: Y:\MIS_DATABASE\Library\ALTIUM_TOOL\SCHEMATICS_PARTS\MS_MOSFET_Library.schlib; Manufacturer: DIODES INC; Mfr_name: DIODES INC; Mistral Part No: 142009070019-R; Package: SOT23-123; Part_type: ICS\POWER\MOSFET; Project: KHAN_MAIN; RoHS: RoHS; Temperature: -55°C+150°C; Tolerance: NA; Voltage: 50V; Wattage: 300mW; Weight: 8mg; Datasheet: Y:\MIS_DATABASE\DATASHEETS\DISCRETES\TRANSISTORS_FETS\BSS138.PDF
U262 = DP83867ERGZT_VQFN48: IC SMALL FORM FACTOR 10/100/1000 Mb/s ETHERNET PHY LAYER TRANSCEIVER VQFN48; Chkd/date: VASANTHA/251115; Crtd /date: VASANTHA/251115; Custom_Duty: 15%; Customs_HS_Code: 85423100; Distributor_name: DIGIKEY; Distributor_part_number: 296-43254-1-ND; Height: 1.00MM; Manufacturer: TEXAS INSTRUMENTS; Mfr_name: TEXAS INSTRUMENTS; Mistral Part No: 143015110004-R; Package: VQFN48; Part_type: ICS\TELECOM\TRANSCEIVER; Project: TI_VLAN_SWITCH; RoHS: RoHS; Temperature: -40°C+105°C; Tolerance: NA; Voltage: NA; Wattage: NA; Weight: NA; Datasheet: Y:\MIS_DATABASE\DATASHEETS\ICS\DIGITAL\BUSTRANSCEIVER\DP83867.PDF
Y13 = CRY: CRY 25.000MHz 18pF SMD; Chkd/date: VASANTHA/110316; Crtd /date: JEBRAN/090216; Custom_Duty: 24%; Customs_HS_Code: 85439000; Distributor_name: DIGIKEY; Distributor_part_number: CTX1175CT-ND; Footprint Path: Y:\MIS_DATABASE\Library\ALTIUM_TOOL\PCB_FOOTPRINTS\Altium_Footprint_Lib.PcbLib; Height: 1.35MM; Library Path: Y:\MIS_DATABASE\Library\ALTIUM_TOOL\SCHEMATICS_PARTS\MS_DISCRETE_Library.schlib; Manufacturer: CTS; Mfr_name: CTS; Mfr_part_number: 445I23D25M00000; Mistral Part No: 130016020016-R; Package: SMD; Part_type: CRYSTAL; Project: PDI_MINIPCB; RoHS: RoHS; Temperature: -40°C+85°C; Tolerance: NA; Voltage: NA; Wattage: NA; Weight: 50mg; Datasheet: Y:\MIS_DATABASE\DATASHEETS\MISC\CRY_OSC\445.PDF
D9-D28 = DIODE_TPD1E05U06: DIODE 1CH ESD PROTECTION FOR INTERFACE X1SON2; Chkd/date: MANIRAJA/290618; Crtd /date: MANIRAJA/290618; Custom_Duty: 15%; Customs_HS_Code: 85412900; Distributor_name: DIGIKEY; Distributor_part_number: 296-39342-1-ND; Footprint Path: Y:\MIS_DATABASE\Library\ALTIUM_TOOL\PCB_FOOTPRINTS\Altium_Footprint_Lib.PcbLib; Height: 0.45MM; Library Path: Y:\MIS_DATABASE\Library\ALTIUM_TOOL\SCHEMATICS_PARTS\MS_DISCRETE_Library.schlib; Manufacturer: TEXAS INSTRUMENTS; Mfr_name: TEXAS INSTRUMENTS; Mfr_part_number: TPD1E05U06DPYT; Mistral Part No: 130018060037-R; Package: X1SON2; Part_type: DIODE\TVS; Project: GOLDEN-I LITE; RoHS: RoHS; Temperature: -40°C+125°C; Tolerance: NA; Voltage: NA; Wattage: NA; Weight: 1mg; Datasheet: Y:\MIS_DATABASE\DATASHEETS\DISCRETES\DIODES\TPDXE05U06.PDF
J8 J9 = CON20_USB_F_TI: CON MINI USB-DISPLAY PORT 20POS FEMALE RT TH; Chkd/date: MANIRAJA/280518; Crtd /date: VASANTHA/05115; Custom_Duty: 24%; Customs_HS_Code: 85369090; Distributor_name: DIGIKEY; Distributor_part_number: WM19271CT-ND; Footprint Path: Y:\MIS_DATABASE\Library\ALTIUM_TOOL\PCB_FOOTPRINTS\Altium_Footprint_Lib.PcbLib; Height: 6.98MM; Library Path: Y:\MIS_DATABASE\Library\ALTIUM_TOOL\SCHEMATICS_PARTS\MS_CONNECTOR_Library.schlib; Library Ref: CON20_USB_F; Manufacturer: MOLEX; Mfr_name: MOLEX; Mfr_part_number: 472720001; Mistral Part No: 150015110011-R; Package: THRU-HOLE; Part_type: CONNECTOR\USB; Project: LRDE_PSPU; RoHS: RoHS; Temperature: -20°C+85°C; Tolerance: NA; Voltage: NA; Wattage: NA; Weight: 2.719g; Datasheet: Y:\MIS_DATABASE\DATASHEETS\CONNECTORS\47272XXX.PDF
L9-L18 = INDUCTOR_DLW31S: IND COMMON MODE CHOKE 90E 280mA SMD; Chkd/date: MANIRAJA/270619; Crtd /date: MANIRAJA/270619; Custom_Duty: 24%; Customs_HS_Code: 85437099; Distributor_name: NA; Distributor_part_number: NA; Footprint Path: Y:\MIS_DATABASE\Library\ALTIUM_TOOL\PCB_FOOTPRINTS\Altium_Footprint_Lib.PcbLib; Height: 1.40MM; Library Path: Y:\MIS_DATABASE\Library\ALTIUM_TOOL\SCHEMATICS_PARTS\MS_DISCRETE_Library.schlib; Manufacturer: MURATA; Mfr_name: MURATA; Mfr_part_number: DLW21SZ900HQ2B; Mistral Part No: 130019060035-R; Package: SMD; Part_type: INDUCTOR; Project: TI_J7ES_CP; RoHS: RoHS; Temperature: -40°C+105°C; Tolerance: NA; Voltage: NA; Wattage: NA; Weight: 11mg; Datasheet: Y:\MIS_DATABASE\DATASHEETS\DISCRETES\INDUCTORS\DLW21SZ900HQ2B.PDF
R42-R45 R759 R760 = RESISTOR: RES 100K 1/10W 5% 0402; Chkd/date: VASANTHA/291216; Crtd /date: GEETHA/190406; Custom_Duty: 15%; Customs_HS_Code: 85332119; Distributor_name: DIGIKEY; Distributor_part_number: P100KJCT-ND; Footprint Path: Y:\MIS_DATABASE\Library\ALTIUM_TOOL\PCB_FOOTPRINTS\Altium_Footprint_Lib.PcbLib; Height: 0.40MM; Library Path: Y:\MIS_DATABASE\Library\ALTIUM_TOOL\SCHEMATICS_PARTS\MS_DISCRETE_Library.schlib; Manufacturer: PANASONIC-ECG; Mfr_name: PANASONIC-ECG; Mfr_part_number: ERJ-2GEJ104X; Mistral Part No: 110009030177-R; Package: 0402; Part_type: RESISTORS\FIXED; Project: RED EYE; RoHS: RoHS; Temperature: -55°C+155°C; Tolerance: 5%; Voltage: NA; Wattage: 1/10W; Weight: 0.8mg; Datasheet: Y:\MIS_DATABASE\DATASHEETS\RESISTORS\PAN-ERJSER_NOV17.PDF
R754 R755 R757 R758 = RESISTOR: RES 0E 1/10W JUMPER 0402; Chkd/date: VASANTHA/061216; Crtd /date: NAVEED/201014; Custom_Duty: 15%; Customs_HS_Code: 85332119; Distributor_name: DIGIKEY; Distributor_part_number: P0.0JCT-ND; Footprint Path: Y:\MIS_DATABASE\Library\ALTIUM_TOOL\PCB_FOOTPRINTS\Altium_Footprint_Lib.PcbLib; Height: 0.40MM; IBISSP_MODLES: VALUE REPEATING 2 TIME; Library Path: Y:\MIS_DATABASE\Library\ALTIUM_TOOL\SCHEMATICS_PARTS\MS_DISCRETE_Library.schlib; Manufacturer: PANASONIC-ECG; Mfr_name: PANASONIC-ECG; Mfr_part_number: ERJ-2GE0R00X; Mistral Part No: 110018030052-R; Package: 0402; Part_type: RESISTORS\FIXED; Project: AEGIS POM; RoHS: RoHS; Temperature: -55°C+155°C; Tolerance: NA; Voltage: NA; Wattage: 1/10W; Weight: 0.8mg; Datasheet: Y:\MIS_DATABASE\DATASHEETS\RESISTORS\PAN-ERJSER_NOV17.PDF
U167 U168 = SN74LVC1G17DCKR_SC70-5: IC SINGLE SCHMITT-TRIGGER BUFFER SC70-5; Chkd/date: MAZHAR/011210; Crtd /date: BAVISH/251110; Custom_Duty: 15%; Customs_HS_Code: 85423100; Distributor_name: DIGIKEY; Distributor_part_number: 296-11934-1-ND; Height: 1.10MM; Mfr_name: TEXAS INSTRUMENTS; Mistral Part No: 141010110012-R; Part_type: ICS\DIGITAL\COMBINATIONAL; Project: ITS-PWR_CARD; RoHS: RoHS; Temperature: -40°C+85°C; Tolerance: NA; Voltage: NA; Wattage: NA; Weight: NA; Datasheet: Y:\MIS_DATABASE\DATASHEETS\ICS\DIGITAL\COMBINATIONAL\SN74LVC1G17DCK.PDF
B1 = BATTERY: BATTERY HOLDER COIN CELL 12MM DIA SMD; Chkd/date: MANIRAJA/091118; Crtd /date: ALVY/091118; Custom_Duty: 15%; Customs_HS_Code: 85322990; Distributor_name: DIGIKEY; Distributor_part_number: BC501SM-TRCT-ND; Footprint Path: Y:\MIS_DATABASE\Library\ALTIUM_TOOL\PCB_FOOTPRINTS\Altium_Footprint_Lib.PcbLib; Height: 4.13MM; Library Path: Y:\MIS_DATABASE\Library\ALTIUM_TOOL\SCHEMATICS_PARTS\MS_DISCRETE_Library.schlib; Manufacturer: MPD; Mfr_name: MPD; Mfr_part_number: BC501SM-TR; Mistral Part No: 130018110011-R; Package: SMD; Part_type: BATTERY HOLDER; Project: TI_J7ES_EVM_CP; RoHS: RoHS; Temperature: -40°C+85°C; Tolerance: NA; Voltage: NA; Wattage: NA; Weight: 860mg; Datasheet: Y:\MIS_DATABASE\DATASHEETS\MISC\BATTERY\BC501SM-TR.PDF
C1172 C1173 = CAP: CAP CERAMIC 18pF 50V 5% HI-Q C0G(NP0) 0402; Automotive Alternate_mfr_name: TDK; Automotive Alternate_mfr_part_number: CGA2B2C0G1H180J050BA; Chkd/date: VASANTHA/030315; Crtd /date: NAVEED/271014; Custom_Duty: 15%; Customs_HS_Code: 85322990; Direct Alternate_mfr_name: KEMET; Direct Alternate_mfr_part_number: CBR04C180J5GAC; Distributor_name: DIGIKEY; Distributor_part_number: 490-3119-1-ND; Footprint Path: Y:\MIS_DATABASE\Library\ALTIUM_TOOL\PCB_FOOTPRINTS\Altium_Footprint_Lib.PcbLib; Height: 0.55MM; Library Path: Y:\MIS_DATABASE\Library\ALTIUM_TOOL\SCHEMATICS_PARTS\MS_DISCRETE_Library.schlib; Manufacturer: MURATA; Mfr_name: MURATA; Mfr_part_number: GJM1555C1H180JB01D; Mistral Part No: 120014100019-R; Package: 0402; Part_type: CAPACITORS\CERAMIC; Project: DC_MIST_RDC; RoHS: RoHS; Temperature: -55°C+125°C; Tolerance: 5%; Voltage: 50V; Wattage: NA; Weight: 6mg; Datasheet: Y:\MIS_DATABASE\DATASHEETS\CAPACITORS\MURATA-GXX-SER_NOV17.PDF
J25 = HEADER_3X1: HDR 1X3 2.54MM PITCH ST TH; Chkd/date: VASANTHA/290616; Crtd /date: VASANTHA/290616; Custom_Duty: 15%; Customs_HS_Code: 85322990; Distributor_name: DIGIKEY; Distributor_part_number: 609-3471-ND; Height: 8.58MM; Manufacturer: FCI; Mfr_name: FCI; Mfr_part_number: 68001-403HLF; Mistral Part No: 150016060025-R; Package: THRU-HOLE; Part_type: CONNECTOR\HEADERS; Project: IKEYP; RoHS: RoHS; Temperature: -40°C+105°C; Tolerance: NA; Voltage: NA; Wattage: NA; Weight: NA; Datasheet: Y:\MIS_DATABASE\DATASHEETS\CONNECTORS\68000.PDF
J26 = HEADER_6X1: CON HDR 6X1 2.54MM PITCH ST TH; Chkd/date: MAZHAR/100311; Crtd /date: BAVISH/210111; Custom_Duty: 24%; Customs_HS_Code: 85369090; Distributor_name: DIGIKEY; Distributor_part_number: A26551-ND; Height: 10.79MM; Manufacturer: TYCO ELECTRONICS; Mfr_name: TYCO ELECTRONICS; Mfr_part_number: 87224-6; Mistral Part No: 150011010025-R; Package: THRU-HOLE; Part_type: CONNECTOR\HEADERS; Project: OMAPL1_PEC20; RoHS: RoHS; Temperature: NA; Tolerance: NA; Voltage: NA; Wattage: NA; Weight: NA; Datasheet: Y:\MIS_DATABASE\DATASHEETS\CONNECTORS\87224-6.PDF
J27 = HEADER_10X2: CON HDR 2X10 2.54MM PITCH ST TH; Chkd/date: NAVEED/140515; Crtd /date: MAZHAR/020909; Custom_Duty: 0.24; Customs_HS_Code: 85369090; Distributor_name: DIGIKEY; Distributor_part_number: SAM1032-10-ND; Height: 5.02MM; Manufacturer: SAMTEC; Mfr_name: SAMTEC; Mfr_part_number: TSW-110-07-S-D; Mistral Part No: 150009090001-R; Package: THRU-HOLE; Part_type: CONNECTOR\HEADERS; Project: SMART VIEW_NVR; RoHS: RoHS; Temperature: NA; Tolerance: NA; Voltage: NA; Wattage: NA; Weight: NA; Datasheet: Y:\MIS_DATABASE\DATASHEETS\CONNECTORS\TSW-106-23-T-S.PDF
R1080 = RESISTOR: RES 1K 1/10W 1% 0402; Chkd/date: VASANTHA/281216; Crtd /date: MAZHAR/150506; Custom_Duty: 15%; Customs_HS_Code: 85332119; Distributor_name: DIGIKEY; Distributor_part_number: P1.00KLCT-ND; Footprint Path: Y:\MIS_DATABASE\Library\ALTIUM_TOOL\PCB_FOOTPRINTS\Altium_Footprint_Lib.PcbLib; Height: 0.40MM; Library Path: Y:\MIS_DATABASE\Library\ALTIUM_TOOL\SCHEMATICS_PARTS\MS_DISCRETE_Library.schlib; Manufacturer: PANASONIC-ECG; Mfr_name: PANASONIC-ECG; Mfr_part_number: ERJ-2RKF1001X; Mistral Part No: 110009030411-R; Package: 0402; Part_type: RESISTORS\FIXED; Project: VOCERA; RoHS: RoHS; Temperature: -55°C+155°C; Tolerance: 1%; Voltage: NA; Wattage: 1/10W; Weight: 0.8mg; Datasheet: Y:\MIS_DATABASE\DATASHEETS\RESISTORS\PAN-ERJSER_NOV17.PDF
TP222 = TESTPOINT: TESTPOINT CIR 40 SMD; Chkd/date: MAZHAR/190505; Crtd /date: MAZHAR/190505; Distributor_name: NA; Distributor_part_number: NA; Footprint Path: Y:\MIS_DATABASE\Library\ALTIUM_TOOL\PCB_FOOTPRINTS\Altium_Footprint_Lib.PcbLib; Height: NA; Library Path: Y:\MIS_DATABASE\Library\ALTIUM_TOOL\SCHEMATICS_PARTS\MS_DISCRETE_Library.schlib; MECHANICAL 3D STEP FILE: NA; Manufacturer: LOCAL; Mfr_name: LOCAL; Mistral Part No: 130009030933; Package: SMD; Project: RAINIER-3; RoHS: NA; Temperature: NA; Tolerance: NA; Voltage: NA; Wattage: NA; Weight: NA; Datasheet: NA
U256 = MCP79410_SOIC8: IC BATTERY-BACKED I2C RTCC WITH SRAM,EEPROM SOIC8; Chkd/date: MANIRAJA/190617; Crtd /date: MANIRAJA/190617; Custom_Duty: 15%; Customs_HS_Code: 85423100; Distributor_name: DIGIKEY; Distributor_part_number: MCP79410-I/SN-ND; Height: 1.75MM; Manufacturer: MICROCHIP; Mfr_name: MICROCHIP; Mistral Part No: 142017060006-R; Package: SOIC8; Part_type: ICS\POWER\BATTERY MANGEMENT; Project: TI_SVB_CONTROLLER CARD; RoHS: RoHS; Temperature: -40°C+85°C; Tolerance: NA; Voltage: NA; Wattage: NA; Weight: 540mg; Datasheet: Y:\MIS_DATABASE\DATASHEETS\ICS\POWER\MCP7941XX.PDF
Y11 = CRY: CRY 32.768KHz 12.5pF SMD; Chkd/date: VASANTHA/050117; Crtd /date: MAZHAR/250907; Custom_Duty: 24%; Customs_HS_Code: 85439000; Distributor_name: DIGIKEY; Distributor_part_number: 535-9542-1-ND; Height: 0.90MM; Manufacturer: ABRACON; Mfr_name: ABRACON; Mfr_part_number: ABS07-32.768KHZ-T; Mistral Part No: 130009030082-R; Package: SMD; Part_type: CRYSTAL; Project: SMART VIEW_IP CAMERA; RoHS: RoHS; Temperature: -40°C+85°C; Tolerance: NA; Voltage: NA; Wattage: NA; Weight: 16mg; Datasheet: Y:\MIS_DATABASE\DATASHEETS\MISC\CRY_OSC\ABS07.PDF

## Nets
DGND: B1.2(-) C22.2 C23.2 C397.2 C422.2 C423.2 C436.2 C442.2 C476.2 C477.2 C478.2 C560.2 C566.2 C1172.2 C1173.2 C1180.2 C1181.2 C1187.2 C1189.2 C1191.2 C1198.2 C1199.2 C1208.1 C1219.1 C1224.2 C1225.2 C1226.2 C1248.1 C1266.2 C1267.2 D9.2(GND) D10.2(GND) D11.2(GND) D12.2(GND) D13.2(GND) D14.2(GND) D15.2(GND) D16.2(GND) D17.2(GND) D18.2(GND) D19.2(GND) D20.2(GND) D21.2(GND) D22.2(GND) D23.2(GND) D24.2(GND) D25.2(GND) D26.2(GND) D27.2(GND) D28.2(GND) J8.2(GND) J8.5(GND) J8.8(GND) J8.11(GND) J8.16(GND) J8.19(RETURN) J8.SH1 J8.SH2 J8.SH3 J8.SH4 J9.2(GND) J9.5(GND) J9.8(GND) J9.11(GND) J9.16(GND) J9.19(RETURN) J9.SH1 J9.SH2 J9.SH3 J9.SH4 J25.1 J26.6 J27.1 J27.7 J27.8 J27.13 J27.14 J27.19 J27.20 J39.1(CH-GND) R42.1 R44.1 R567.1 R621.2 R654.2 R697.1 R754.2 R755.2 R757.2 R758.2 R759.1 R760.1 R1199.2 R1200.2 R1224.2 R1232.2 R1254.2 R1256.2 R1259.1 U107.3(GND) U126.2(SOURCE) U140.2(SOURCE) U167.3(GND) U168.3(GND) U256.4(VSS) U262.49(EP) U272.2(SOURCE) ; also on sheet 11 12 13 14 15 16 17 18 20 21 22 23 24 25 26 27 28 29 30 31 32 33 34 35 36 37 38 39 40 41 42 43 44 45 46 47 48 49 50 51 52 53 54 55 59 60 61 62 63 64 65 66 67 68 69 70 71 72 73 76 77 78 79 81 82 83 84
V3V3_DP0: C23.1 C560.1 J9.20(PWR) ; also on sheet 68
V3V3_DP1: C22.1 C566.1 J8.20(PWR) ; also on sheet 68
VBAT_RTC: B1.1(+) U256.3(VBAT)
VCC_1V1: C423.1 C442.1 C477.1 C1180.1 C1181.1 C1191.1 C1225.1 U262.6(VDDA1P0) U262.24(VDD1P0) U262.31(VDD1P0) U262.42(VDD1P0) ; also on sheet 51 68
VDD_2V5: C476.1 C478.1 C1224.1 C1226.1 U262.3(VDDA2P5) U262.9(VDDA2P5) ; also on sheet 68
CON_DP0_AUX_N: D28.1(I/O) J9.17(AUX_CH_N) L18.2(IN2) R45.1
CON_DP0_AUX_P: D27.1(I/O) J9.15(AUX_CH_P) L18.3(OUT1) R44.2
CON_DP0_TX0_N: D20.1(I/O) J9.3(ML_L0_N) L14.2(IN2)
CON_DP0_TX0_P: D19.1(I/O) J9.1(ML_L0_P) L14.3(OUT1)
CON_DP0_TX1_N: D14.1(I/O) J9.6(ML_L1_N) L11.2(IN2)
CON_DP0_TX1_P: D13.1(I/O) J9.4(ML_L1_P) L11.3(OUT1)
CON_DP0_TX2_N: D26.1(I/O) J9.9(ML_L2_N) L16.2(IN2)
CON_DP0_TX2_P: D25.1(I/O) J9.7(ML_L2_P) L16.3(OUT1)
CON_DP0_TX3_N: D16.1(I/O) J9.12(ML_L3_N) L12.2(IN2)
CON_DP0_TX3_P: D15.1(I/O) J9.10(ML_L3_P) L12.3(OUT1)
CON_DP1_AUX_N: D24.1(I/O) J8.17(AUX_CH_N) L17.2(IN2) R43.1
CON_DP1_AUX_P: D23.1(I/O) J8.15(AUX_CH_P) L17.3(OUT1) R42.2
CON_DP1_TX0_N: D18.1(I/O) J8.3(ML_L0_N) L13.2(IN2)
CON_DP1_TX0_P: D17.1(I/O) J8.1(ML_L0_P) L13.3(OUT1)
CON_DP1_TX1_N: D10.1(I/O) J8.6(ML_L1_N) L9.2(IN2)
CON_DP1_TX1_P: D9.1(I/O) J8.4(ML_L1_P) L9.3(OUT1)
CON_DP1_TX2_N: D22.1(I/O) J8.9(ML_L2_N) L15.2(IN2)
CON_DP1_TX2_P: D21.1(I/O) J8.7(ML_L2_P) L15.3(OUT1)
CON_DP1_TX3_N: D12.1(I/O) J8.12(ML_L3_N) L10.2(IN2)
CON_DP1_TX3_P: D11.1(I/O) J8.10(ML_L3_P) L10.3(OUT1)
DP0_AUX_N: L18.1(IN1) ; also on sheet 12
DP0_AUX_P: L18.4(OUT2) ; also on sheet 12
DP0_CONFIG1: J9.13(CONFIG1) R757.1
DP0_CONFIG2: J9.14(CONFIG2) R754.1
DP0_HPD: J9.18(HPD) R759.2 U167.2(A)
DP0_HPD_BUF: U167.4(Y) ; also on sheet 20
DP0_TX0_N: L14.1(IN1) ; also on sheet 13
DP0_TX0_P: L14.4(OUT2) ; also on sheet 13
DP0_TX1_N: L11.1(IN1) ; also on sheet 13
DP0_TX1_P: L11.4(OUT2) ; also on sheet 13
DP0_TX2_N: L16.1(IN1) ; also on sheet 13
DP0_TX2_P: L16.4(OUT2) ; also on sheet 13
DP0_TX3_N: L12.1(IN1) ; also on sheet 13
DP0_TX3_P: L12.4(OUT2) ; also on sheet 13
DP1_AUX_N: L17.1(IN1) ; also on sheet 61
DP1_AUX_P: L17.4(OUT2) ; also on sheet 61
DP1_CONFIG1: J8.13(CONFIG1) R758.1
DP1_CONFIG2: J8.14(CONFIG2) R755.1
DP1_HPD: J8.18(HPD) R760.2 U168.2(A)
DP1_HPD_BUF: U168.4(Y) ; also on sheet 61
DP1_TX0_N: L13.1(IN1) ; also on sheet 61
DP1_TX0_P: L13.4(OUT2) ; also on sheet 61
DP1_TX1_N: L9.1(IN1) ; also on sheet 61
DP1_TX1_P: L9.4(OUT2) ; also on sheet 61
DP1_TX2_N: L15.1(IN1) ; also on sheet 61
DP1_TX2_P: L15.4(OUT2) ; also on sheet 61
DP1_TX3_N: L10.1(IN1) ; also on sheet 61
DP1_TX3_P: L10.4(OUT2) ; also on sheet 61
GPIO_RGMII1_RST#: R561.1 R567.2 U107.2(B) ; also on sheet 38
I2C0_SCL: U256.6(SCL) ; also on sheet 20 32 33 34 38 59
I2C0_SDA: U256.5(SDA) ; also on sheet 20 32 33 34 38 59
MCU_ADC0_AIN0: J27.4 ; also on sheet 21
MCU_ADC0_AIN1: J27.5 ; also on sheet 21
MCU_ADC0_AIN2: J27.11 ; also on sheet 21
MCU_ADC0_AIN3: J27.2 ; also on sheet 21
MCU_ADC0_AIN4: J27.9 ; also on sheet 21
MCU_ADC0_AIN5: J27.15 ; also on sheet 21
MCU_ADC0_AIN6: J27.6 ; also on sheet 21
MCU_ADC0_AIN7: J27.3 ; also on sheet 21
MCU_ADC1_AIN0: J27.17 ; also on sheet 21 30
MCU_ADC1_AIN1: J27.18 ; also on sheet 21 30
MCU_ADC_EXT_TRIGGER0: J27.16 ; also on sheet 18
MCU_ETH_EARTH: C1248.2 J39.15(SH1) J39.16(SH2) R697.2 ; also on sheet 55
MCU_I3C0_SCL: J25.3 ; also on sheet 18 21
MCU_I3C0_SDA: J25.2 R1080.1 ; also on sheet 18 21
MCU_I3C0_SDAPULLEN: R1080.2 ; also on sheet 18
R_MCU_ADC0_REF_N: J27.12 ; also on sheet 21
R_MCU_ADC0_REF_P: J27.10 ; also on sheet 21
RGMII1_100Mbps: J39.14 R1291.1 U126.3(DRAIN)
RGMII1_1000Mbps: J39.13 R1289.1 U272.3(DRAIN)
RGMII1_ACT_LED: J39.12 U140.3(DRAIN)
RGMII1_CLK_OUT: TP229.1(TP) U262.18(CLK_OUT)
RGMII1_D0_N: J39.10(MX0-) U262.2(TD_M_A)
RGMII1_D0_P: J39.9(MX0+) U262.1(TD_P_A)
RGMII1_D1_N: J39.8(MX1-) U262.5(TD_M_B)
RGMII1_D1_P: J39.7(MX1+) U262.4(TD_P_B)
RGMII1_D2_N: J39.6(MX2-) U262.8(TD_M_C)
RGMII1_D2_P: J39.5(MX2+) U262.7(TD_P_C)
RGMII1_D3_N: J39.4(MX3-) U262.11(TD_M_D)
RGMII1_D3_P: J39.3(MX3+) U262.10(TD_P_D)
RGMII1_GPIO0_100: R621.1 R629.2 U126.1(GATE) U262.39(GPIO_0)
RGMII1_GPIO1: R1232.1 R1235.2 U262.40(GPIO_1)
RGMII1_INT#: R1245.1 U262.44(INT/PWDN) ; also on sheet 19
RGMII1_LED0: R649.2 R654.1 U262.47(LED0)
RGMII1_LED1_1000: R1256.1 R1261.2 U262.46(LED1) U272.1(GATE)
RGMII1_LED2_ACT: R1249.2 R1254.1 U140.1(GATE) U262.45(LED2)
RGMII1_LED2_ANODE: J39.11 R1288.1
RGMII1_MDIO0_MDC: U262.16(MDC) ; also on sheet 19
RGMII1_MDIO0_MDIO: U262.17(MDIO) ; also on sheet 19
RGMII1_RBIAS: R1259.2 U262.12(RBIAS)
RGMII1_RD0: R1202.1 ; also on sheet 19
RGMII1_RD0_R: R1200.1 R1202.2 R1218.2 U262.33(RX_D0/SGMII_COP)
RGMII1_RD1: R1213.1 ; also on sheet 19
RGMII1_RD1_R: R1213.2 U262.34(RX_D1/SGMII_CON)
RGMII1_RD2: R1201.1 ; also on sheet 19
RGMII1_RD2_R: R1199.1 R1201.2 R1217.2 U262.35(RX_D2/SGMII_SOP)
RGMII1_RD3: R1212.1 ; also on sheet 19
RGMII1_RD3_R: R1212.2 U262.36(RX_D3/SGMII_SON)
RGMII1_RESET_N: U107.4(Y) U262.43(RESET_N)
RGMII1_RX_CTL: R1205.1 ; also on sheet 19
RGMII1_RX_CTL_R: R1205.2 R1221.2 R1224.1 U262.38(RX_CTRL)
RGMII1_RXC: R1214.1 ; also on sheet 19
RGMII1_RXC_R: R1214.2 U262.32(RX_CLK)
RGMII1_TD0: U262.28(TX_D0/SGMII_SIN) ; also on sheet 19
RGMII1_TD1: U262.27(TX_D1/SGMII_SIP) ; also on sheet 19
RGMII1_TD2: U262.26(TX_D2) ; also on sheet 19
RGMII1_TD3: U262.25(TX_D3) ; also on sheet 19
RGMII1_TX_CTL: U262.37(TX_CTRL) ; also on sheet 19
RGMII1_TXC: U262.29(GTX_CLK) ; also on sheet 19
RGMII1_XIN: C1208.2 U262.15(X_I) Y13.2
RGMII1_XOUT: C1219.2 U262.14(X_O) Y13.1
RTC_REF_CLK: R624.2 TP222.1(TP) U256.7(MFP) ; also on sheet 18
RTC_XIN: C1173.1 U256.1(X1) Y11.2
RTC_XOUT: C1172.1 U256.2(X2) Y11.1
SOC_PORZ_OUT: U107.1(A) ; also on sheet 18 30 32 37 43 51 59 60 62 69
SPI5_CLK: J26.1 ; also on sheet 19
SPI5_CS0: J26.5 ; also on sheet 19
SPI5_CS1: J26.4 ; also on sheet 19
SPI5_D0: J26.2 ; also on sheet 19
SPI5_D1: J26.3 ; also on sheet 19
VSYS_IO_3V3: C397.1 C422.1 C436.1 C1187.1 C1189.1 C1198.1 C1199.1 C1266.1 C1267.1 R43.2 R45.2 R561.2 R624.1 R629.1 R649.1 R1217.1 R1218.1 R1221.1 R1235.1 R1245.2 R1249.1 R1261.1 R1288.2 R1289.2 R1291.2 U107.5(VCC) U167.5(VCC) U168.5(VCC) U256.8(VCC) U262.19(VDDIO) U262.30(VDDIO) U262.41(VDDIO) ; also on sheet 18 20 22 24 29 30 31 32 33 35 36 37 38 40 41 42 43 45 46 48 50 51 53 59 60 61 65 66 68 75 81 82
N32640257: TP235.1(TP) U262.13(VDDA1P8) U262.48(VDDA1P8)

Not connected (* = marked no-connect by the designer): J39 2(VCC)*; U167 1(NC)*; U168 1(NC)*; U262 20(JTAG_CLK)* 21(JTAG_TDO)* 22(JTAG_TMS)* 23(JTAG_TDI)*

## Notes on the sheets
sheet 56
- RGMII1
- VDD1P0 supply voltage is connected to VCC_1V1.
  VDD1P0 supply range is 0.95V to 1.155V
- RJ45
- 100E
- 100E
- 100E
- 100E
- RESET LOGIC
- Silk Screen : "RGMII1"
- RJ45-LED
- FUNCTION
- RIGHT - GREEN
- ACTIVITY
- LEFT  - GREEN
- 1000Mbps Speed
- SPEED AND ACTIVITY LED DRIVERS
- LEFT  - YELLOW
- 100Mbps Speed
- Set Mode 3 [Autoneg Disable - 0]
- PHY ADD = 00000
- Auto_neg = Enabled
  ANEGsel 10/100/1000
- RGMII Clock Skew TX = 0ns
  RGMII Clock Skew RX = 2ns
- LED_2-MODE1 & LED_1-MODE2-TX SKEW=0nS
- GPIO0-MODE1 & GPIO1-MODE1-RX SKEW=2nS
sheet 57
- DISPLAY PORT INTERFACE
- Display Port Connector1
- 100E
- 100E
- 100E
- 100E
- Silkscreen: "DISPLAY_
  PORT0"
- PCB Note: Place the ESD diodes close to DISPLAY  PORT CONN1
- 100E
- Display Port Connector2
- 100E
- 100E
- Silkscreen: "DISPLAY
  _PORT1"
- 100E
- 100E
- PCB Note: Place the ESD diodes close to DISPLAY  PORT CONN2
- 100E
sheet 58
- RTC
- SPI Header
- To SOC
- 7'b I2C Address: 0x57,0x6F
- ADC INTERFACE
- I3C Header
- Silk Screen MCU-I3C
- ADC Connector
